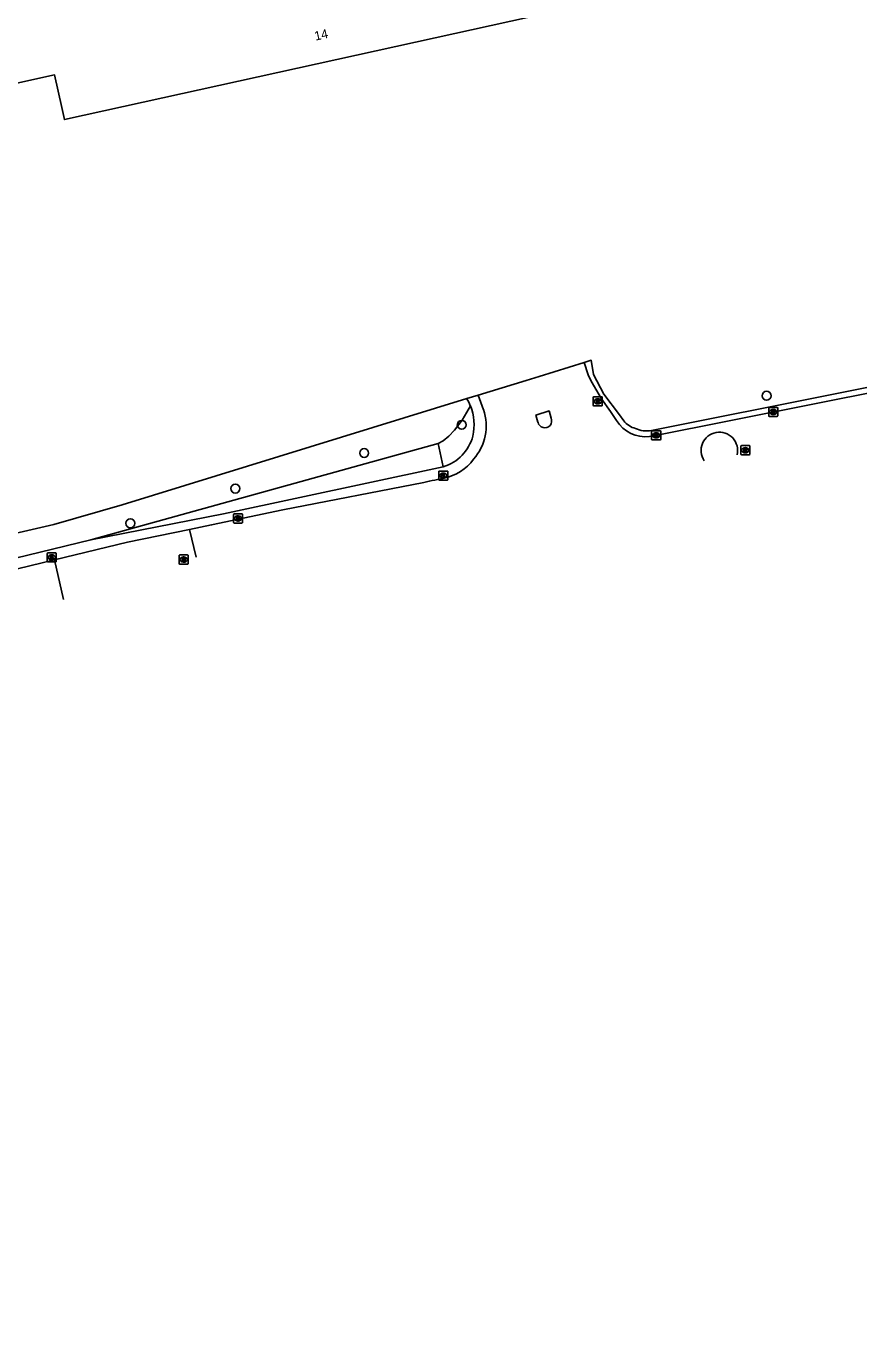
# Model space of a CAD drawing. Extents: x 161477 to 163040, y 383680 to 384868.
# Drawn here: x 162250.6 to 162341.9, y 383711.9 to 383855.4 of the extents above; entities that cross this region are included whole.
import ezdxf

# ---------------------------------------------------------------- set-up
doc = ezdxf.new("R2010")
doc.units = 0
for name, color, linetype in [('IMGEO_Boom', 7, 'Continuous'), ('IMGEO_Groenvoorziening', 7, 'Continuous'), ('IMGEO_Hek', 7, 'Continuous'), ('IMGEO_Kolk', 7, 'Continuous'), ('IMGEO_Pand', 7, 'Continuous'), ('IMGEO_Pand_nummerreeks', 7, 'Continuous'), ('IMGEO_Rijbaan_lokaal_open', 7, 'Continuous'), ('IMGEO_Rioolput', 7, 'Continuous'), ('IMGEO_Voetpad_open', 7, 'Continuous')]:
    doc.layers.add(name, color=color, linetype=linetype)

msp = doc.modelspace()

# ---------------------------------------------------------------- linework, layer by layer
at = {"layer": 'IMGEO_Boom'}
for centre in [(162331.79, 383814.88), (162298.35, 383811.69), (162287.64, 383808.59), (162273.51, 383804.69), (162261.99, 383800.88)]:
    msp.add_circle(centre, 0.489, dxfattribs=at)
at = {"layer": 'IMGEO_Groenvoorziening'}
for points in [[(162298.92, 383814.56), (162261.09, 383802.89), (162253.58, 383800.74), (162226.94, 383794.59), (162215.71, 383792.24), (162200.21, 383788.99), (162072.88, 383760.06), (162061.02, 383757.62), (162034.23, 383752.62), (161913.96, 383727.2), (161882.57, 383720.16), (161862.58, 383715.7), (161851.78, 383713.8), (161847.77, 383713.09), (161846.44, 383712.85), (161845.48, 383712.89), (161845.45, 383711.91)], [(162299.3, 383813.78), (162298.92, 383813.07), (162298.41, 383812.2), (162297.55, 383811.11), (162296.93, 383810.45), (162296.29, 383809.94), (162295.76, 383809.64)], [(162295.76, 383809.64), (162257.67, 383799.06)], [(162296.32, 383807.07), (162295.76, 383809.64)]]:
    msp.add_lwpolyline(points, dxfattribs=at)
at = {"layer": 'IMGEO_Hek'}
msp.add_lwpolyline([(162215.71, 383792.24), (162226.94, 383794.59), (162253.58, 383800.74), (162261.09, 383802.89), (162298.92, 383814.56)], dxfattribs=at)
at = {"layer": 'IMGEO_Kolk'}
for p, q in [((162332.03, 383812.67), (162332.03, 383813.53)), ((162332.1, 383813.6), (162332.96, 383813.6)), ((162332.52, 383813.38), (162332.54, 383813.38)), ((162333.03, 383813.53), (162333.03, 383812.67)), ((162332.96, 383812.6), (162332.1, 383812.6)), ((162332.54, 383812.82), (162332.51, 383812.82)), ((162319.18, 383810.11), (162319.18, 383810.96)), ((162319.26, 383811.03), (162320.11, 383811.03)), ((162319.67, 383810.81), (162319.7, 383810.81)), ((162320.18, 383810.96), (162320.18, 383810.11)), ((162320.11, 383810.03), (162319.26, 383810.03)), ((162319.69, 383810.25), (162319.67, 383810.25)), ((162295.82, 383805.68), (162295.82, 383806.54)), ((162295.9, 383806.61), (162296.75, 383806.61)), ((162296.31, 383806.39), (162296.34, 383806.39)), ((162296.82, 383806.54), (162296.82, 383805.68)), ((162296.75, 383805.61), (162295.9, 383805.61)), ((162296.33, 383805.83), (162296.31, 383805.83)), ((162273.3, 383800.99), (162273.3, 383801.84)), ((162273.38, 383801.91), (162274.23, 383801.91)), ((162274.3, 383801.84), (162274.3, 383800.99)), ((162274.23, 383800.91), (162273.38, 383800.91)), ((162273.79, 383801.69), (162273.81, 383801.69)), ((162273.81, 383801.13), (162273.79, 383801.13)), ((162252.86, 383796.71), (162252.86, 383797.56)), ((162252.93, 383797.64), (162253.79, 383797.64)), ((162253.86, 383797.56), (162253.86, 383796.71)), ((162253.79, 383796.64), (162252.93, 383796.64)), ((162253.35, 383797.42), (162253.37, 383797.42)), ((162253.37, 383796.86), (162253.35, 383796.86))]:
    msp.add_line(p, q, dxfattribs=at)
for points in [[(162332.03, 383812.67), (162332.03, 383813.53)], [(162332.1, 383813.6), (162332.96, 383813.6)], [(162332.35, 383813.3), (162332.47, 383813.3), (162332.47, 383813.15), (162332.6, 383813.3), (162332.77, 383813.3), (162332.62, 383813.15), (162332.77, 383812.9), (162332.62, 383812.9), (162332.54, 383813.06), (162332.47, 383813), (162332.47, 383812.9), (162332.35, 383812.9), (162332.35, 383813.3)], [(162333.03, 383813.53), (162333.03, 383812.67)], [(162332.96, 383812.6), (162332.1, 383812.6)], [(162319.18, 383810.11), (162319.18, 383810.96)], [(162319.26, 383811.03), (162320.11, 383811.03)], [(162319.5, 383810.73), (162319.63, 383810.73), (162319.63, 383810.58), (162319.76, 383810.73), (162319.92, 383810.73), (162319.77, 383810.58), (162319.93, 383810.33), (162319.77, 383810.33), (162319.69, 383810.5), (162319.63, 383810.43), (162319.63, 383810.33), (162319.5, 383810.33), (162319.5, 383810.73)], [(162320.18, 383810.96), (162320.18, 383810.11)], [(162320.11, 383810.03), (162319.26, 383810.03)], [(162295.82, 383805.68), (162295.82, 383806.54)], [(162295.9, 383806.61), (162296.75, 383806.61)], [(162296.14, 383806.31), (162296.27, 383806.31), (162296.27, 383806.16), (162296.4, 383806.31), (162296.56, 383806.31), (162296.42, 383806.16), (162296.57, 383805.91), (162296.42, 383805.91), (162296.33, 383806.07), (162296.27, 383806.01), (162296.27, 383805.91), (162296.14, 383805.91), (162296.14, 383806.31)], [(162296.82, 383806.54), (162296.82, 383805.68)], [(162296.75, 383805.61), (162295.9, 383805.61)], [(162273.3, 383800.99), (162273.3, 383801.84)], [(162273.38, 383801.91), (162274.23, 383801.91)], [(162274.3, 383801.84), (162274.3, 383800.99)], [(162274.23, 383800.91), (162273.38, 383800.91)], [(162273.62, 383801.61), (162273.75, 383801.61), (162273.75, 383801.46), (162273.87, 383801.61), (162274.04, 383801.61), (162273.89, 383801.46), (162274.05, 383801.21), (162273.89, 383801.21), (162273.81, 383801.38), (162273.75, 383801.31), (162273.75, 383801.21), (162273.62, 383801.21), (162273.62, 383801.61)], [(162252.86, 383796.71), (162252.86, 383797.56)], [(162252.93, 383797.64), (162253.79, 383797.64)], [(162253.86, 383797.56), (162253.86, 383796.71)], [(162253.79, 383796.64), (162252.93, 383796.64)], [(162253.18, 383797.34), (162253.3, 383797.34), (162253.3, 383797.19), (162253.43, 383797.34), (162253.6, 383797.34), (162253.45, 383797.19), (162253.6, 383796.94), (162253.45, 383796.94), (162253.37, 383797.1), (162253.3, 383797.03), (162253.3, 383796.94), (162253.18, 383796.94), (162253.18, 383797.34)]]:
    msp.add_lwpolyline(points, dxfattribs=at)
for centre, start, end in [((162332.11, 383813.52), 91.552, 178.448), ((162332.11, 383813.52), 91.552, 178.448), ((162332.95, 383813.52), 1.552, 88.448), ((162332.95, 383813.52), 1.552, 88.448), ((162332.11, 383812.68), 181.552, 268.448), ((162332.11, 383812.68), 181.552, 268.448), ((162332.95, 383812.68), 271.552, 358.448), ((162332.95, 383812.68), 271.552, 358.448), ((162319.26, 383810.96), 91.552, 178.448), ((162319.26, 383810.96), 91.552, 178.448), ((162320.11, 383810.96), 1.552, 88.448), ((162320.11, 383810.96), 1.552, 88.448), ((162319.26, 383810.11), 181.552, 268.448), ((162319.26, 383810.11), 181.552, 268.448), ((162320.11, 383810.11), 271.552, 358.448), ((162320.11, 383810.11), 271.552, 358.448), ((162295.9, 383806.53), 91.552, 178.448), ((162295.9, 383806.53), 91.552, 178.448), ((162296.75, 383806.53), 1.552, 88.448), ((162296.75, 383806.53), 1.552, 88.448), ((162295.9, 383805.69), 181.552, 268.448), ((162295.9, 383805.69), 181.552, 268.448), ((162296.75, 383805.69), 271.552, 358.448), ((162296.75, 383805.69), 271.552, 358.448), ((162273.38, 383801.84), 91.552, 178.448), ((162273.38, 383801.84), 91.552, 178.448), ((162274.23, 383801.84), 1.552, 88.448), ((162274.23, 383801.84), 1.552, 88.448), ((162273.38, 383800.99), 181.552, 268.448), ((162273.38, 383800.99), 181.552, 268.448), ((162274.23, 383800.99), 271.552, 358.448), ((162274.23, 383800.99), 271.552, 358.448), ((162252.94, 383797.56), 91.552, 178.448), ((162252.94, 383797.56), 91.552, 178.448), ((162253.78, 383797.56), 1.552, 88.448), ((162253.78, 383797.56), 1.552, 88.448), ((162252.94, 383796.71), 181.552, 268.448), ((162252.94, 383796.71), 181.552, 268.448), ((162253.78, 383796.71), 271.552, 358.448), ((162253.78, 383796.71), 271.552, 358.448)]:
    msp.add_arc(centre, 0.0765, start, end, dxfattribs=at)
for centre, major_axis, ratio, start_param, end_param in [((162332.52, 383813.1), (-0.387, 0.002), 0.722429, 4.712389, 7.853982), ((162332.54, 383813.1), (-0.39, 0.002), 0.717154, 1.570796, 4.712389), ((162319.67, 383810.53), (-0.387, 0.002), 0.722429, 4.712389, 7.853982), ((162319.69, 383810.53), (-0.39, 0.002), 0.717154, 1.570796, 4.712389), ((162296.31, 383806.11), (-0.387, 0.002), 0.722429, 4.712389, 7.853982), ((162296.33, 383806.11), (-0.39, 0.002), 0.717154, 1.570796, 4.712389), ((162273.79, 383801.41), (-0.387, 0.002), 0.722429, 4.712389, 7.853982), ((162273.81, 383801.41), (-0.39, 0.002), 0.717154, 1.570796, 4.712389), ((162253.35, 383797.14), (-0.387, 0.002), 0.722429, 4.712389, 7.853982), ((162253.37, 383797.14), (-0.39, 0.002), 0.717154, 1.570796, 4.712389)]:
    msp.add_ellipse(centre, major_axis=major_axis, ratio=ratio, start_param=start_param, end_param=end_param, dxfattribs=at)
at = {"layer": 'IMGEO_Pand'}
msp.add_lwpolyline([(162222.78, 383843.26), (162253.68, 383850.09), (162254.46, 383846.53), (162254.76, 383845.19), (162312.37, 383857.91), (162312.05, 383859.38), (162421.56, 383883.57), (162417.41, 383902.34), (162405.62, 383899.74)], dxfattribs=at)
at = {"layer": 'IMGEO_Rijbaan_lokaal_open'}
for points in [[(162395.79, 383826.38), (162380.16, 383823.26), (162319.15, 383811.08)], [(162379.65, 383822.47), (162319.24, 383810.45), (162318.95, 383810.39)], [(162311.78, 383818.53), (162306.83, 383817), (162305.42, 383816.57), (162300.16, 383814.95)], [(162316.14, 383812.14), (162315.67, 383812.77), (162313.95, 383815.04), (162312.8, 383817.2), (162312.56, 383818.77), (162311.78, 383818.53)], [(162315.33, 383812.15), (162314.66, 383813.15), (162313.68, 383814.54), (162312.55, 383816.49), (162312.22, 383817.18), (162311.78, 383818.53)], [(162300.16, 383814.95), (162300.74, 383813.35)], [(162306.71, 383811.97), (162306.49, 383812.75), (162307.92, 383813.21), (162308.15, 383812.42)], [(162296.37, 383805.82), (162296.01, 383805.74), (162295.7, 383805.68), (162295.4, 383805.62), (162295.09, 383805.56), (162294.79, 383805.49), (162294.48, 383805.43), (162294.18, 383805.37), (162278.73, 383802.34), (162270.9, 383800.71), (162268.48, 383800.21)], [(162268.48, 383800.21), (162261.67, 383798.79), (162253.66, 383796.86)], [(162269.21, 383797.16), (162268.48, 383800.21)], [(162253.66, 383796.86), (162244.29, 383794.61), (162240.84, 383793.55), (162224.8, 383788.56), (162219.62, 383786.85), (162219.33, 383786.78), (162214.48, 383785.25), (162201.98, 383781.65), (162200.19, 383781.17), (162199.34, 383780.94), (162193.85, 383779.62), (162173.23, 383775.14), (162160.65, 383772.41), (162129.52, 383765.69), (162103.41, 383760.08), (162086.49, 383756.59), (162061.51, 383751.2), (162055.16, 383749.81), (162038.61, 383746.29), (162000, 383738.01)], [(162253.66, 383796.86), (162254.66, 383792.5)]]:
    msp.add_lwpolyline(points, dxfattribs=at)
for centre, radius, start, end in [((162295.45, 383811.59), 5.58, 318.7426, 18.4435), ((162307.46, 383812.11), 0.759, 190.181, 24.5952), ((162318.53, 383814.12), 3.75, 211.5389, 276.3751), ((162317.96, 383813.5), 2.28, 216.7152, 256.2761), ((162318.57, 383813.49), 2.48, 242.3013, 283.5464), ((162326.61, 383808.88), 2, 100.0945, 214.3745), ((162326.61, 383808.88), 2, 345.8313, 100.0996), ((162295.24, 383811.21), 5.51, 281.859, 323.1128)]:
    msp.add_arc(centre, radius, start, end, dxfattribs=at)
at = {"layer": 'IMGEO_Rioolput'}
for p, q in [((162312.77, 383813.84), (162312.77, 383814.69)), ((162312.84, 383814.76), (162313.69, 383814.76)), ((162313.77, 383814.69), (162313.77, 383813.84)), ((162313.69, 383813.76), (162312.84, 383813.76)), ((162313.25, 383814.54), (162313.28, 383814.54)), ((162313.28, 383813.98), (162313.25, 383813.98)), ((162328.96, 383808.48), (162328.96, 383809.33)), ((162329.04, 383809.41), (162329.89, 383809.41)), ((162329.45, 383809.18), (162329.47, 383809.18)), ((162329.96, 383809.33), (162329.96, 383808.48)), ((162329.89, 383808.4), (162329.04, 383808.4)), ((162329.47, 383808.63), (162329.45, 383808.63)), ((162267.33, 383796.47), (162267.33, 383797.32)), ((162267.41, 383797.4), (162268.26, 383797.4)), ((162268.26, 383796.4), (162267.41, 383796.4)), ((162267.82, 383797.18), (162267.85, 383797.18)), ((162267.84, 383796.62), (162267.82, 383796.62)), ((162268.34, 383797.32), (162268.34, 383796.47))]:
    msp.add_line(p, q, dxfattribs=at)
for points in [[(162312.77, 383813.84), (162312.77, 383814.69)], [(162312.84, 383814.76), (162313.69, 383814.76)], [(162313.77, 383814.69), (162313.77, 383813.84)], [(162313.69, 383813.76), (162312.84, 383813.76)], [(162313.35, 383814.46), (162313.1, 383814.46), (162313.1, 383814.06)], [(162313.1, 383814.06), (162313.23, 383814.06), (162313.23, 383814.23), (162313.24, 383814.23)], [(162313.28, 383814.38), (162313.23, 383814.38), (162313.23, 383814.3)], [(162313.23, 383814.3), (162313.28, 383814.3)], [(162313.28, 383814.2), (162313.36, 383814.06), (162313.49, 383814.06), (162313.43, 383814.19)], [(162328.96, 383808.48), (162328.96, 383809.33)], [(162329.04, 383809.41), (162329.89, 383809.41)], [(162329.55, 383809.1), (162329.3, 383809.1), (162329.3, 383808.7)], [(162329.48, 383809.02), (162329.42, 383809.02), (162329.42, 383808.94)], [(162329.42, 383808.94), (162329.47, 383808.94)], [(162329.96, 383809.33), (162329.96, 383808.48)], [(162329.89, 383808.4), (162329.04, 383808.4)], [(162329.3, 383808.7), (162329.42, 383808.7), (162329.42, 383808.87), (162329.43, 383808.87)], [(162329.48, 383808.84), (162329.55, 383808.7), (162329.69, 383808.7), (162329.63, 383808.83)], [(162267.33, 383796.47), (162267.33, 383797.32)], [(162267.41, 383797.4), (162268.26, 383797.4)], [(162268.26, 383796.4), (162267.41, 383796.4)], [(162267.92, 383797.1), (162267.67, 383797.1), (162267.67, 383796.7)], [(162267.67, 383796.7), (162267.8, 383796.7), (162267.8, 383796.86), (162267.81, 383796.86)], [(162267.85, 383797.02), (162267.8, 383797.02), (162267.8, 383796.94)], [(162267.8, 383796.94), (162267.85, 383796.94)], [(162267.85, 383796.83), (162267.92, 383796.7), (162268.06, 383796.7), (162268, 383796.82)], [(162268.34, 383797.32), (162268.34, 383796.47)]]:
    msp.add_lwpolyline(points, dxfattribs=at)
for centre, radius, start, end in [((162312.84, 383814.69), 0.0765, 91.552, 178.448), ((162312.84, 383814.69), 0.0765, 91.552, 178.448), ((162313.69, 383814.69), 0.0765, 1.552, 88.448), ((162313.69, 383814.69), 0.0765, 1.552, 88.448), ((162312.84, 383813.84), 0.0765, 181.552, 268.448), ((162312.84, 383813.84), 0.0765, 181.552, 268.448), ((162313.24, 383814.17), 0.0533, 26.0293, 88.6989), ((162313.29, 383814.29), 0.0964, 77.0061, 93.1865), ((162313.26, 383814.49), 0.19, 274.7715, 282.9687), ((162313.3, 383814.34), 0.0378, 276.6634, 79.6772), ((162313.35, 383814.35), 0.109, 350.3612, 89.416), ((162313.35, 383814.35), 0.112, 277.5842, 350.9817), ((162313.34, 383814.14), 0.108, 29.5134, 73.7905), ((162313.69, 383813.84), 0.0765, 271.552, 358.448), ((162313.69, 383813.84), 0.0765, 271.552, 358.448), ((162329.04, 383809.33), 0.0765, 91.552, 178.448), ((162329.04, 383809.33), 0.0765, 91.552, 178.448), ((162329.46, 383809.13), 0.19, 274.7715, 282.9687), ((162329.48, 383808.93), 0.0964, 77.0061, 93.1865), ((162329.5, 383808.98), 0.0378, 276.6634, 79.6772), ((162329.55, 383808.99), 0.109, 350.3612, 89.416), ((162329.55, 383808.99), 0.112, 277.5842, 350.9817), ((162329.89, 383809.33), 0.0765, 1.552, 88.448), ((162329.89, 383809.33), 0.0765, 1.552, 88.448), ((162329.04, 383808.48), 0.0765, 181.552, 268.448), ((162329.04, 383808.48), 0.0765, 181.552, 268.448), ((162329.43, 383808.81), 0.0533, 26.0293, 88.6989), ((162329.53, 383808.78), 0.108, 29.5134, 73.7905), ((162329.89, 383808.48), 0.0765, 271.552, 358.448), ((162329.89, 383808.48), 0.0765, 271.552, 358.448), ((162267.41, 383797.32), 0.0765, 91.552, 178.448), ((162267.41, 383797.32), 0.0765, 91.552, 178.448), ((162267.41, 383796.47), 0.0765, 181.552, 268.448), ((162267.41, 383796.47), 0.0765, 181.552, 268.448), ((162267.8, 383796.81), 0.0533, 26.0293, 88.6989), ((162267.85, 383796.92), 0.0964, 77.0061, 93.1865), ((162267.83, 383797.13), 0.19, 274.7715, 282.9687), ((162267.87, 383796.98), 0.0378, 276.6634, 79.6772), ((162267.92, 383796.99), 0.109, 350.3612, 89.416), ((162267.92, 383796.99), 0.112, 277.5842, 350.9817), ((162267.9, 383796.77), 0.108, 29.5134, 73.7905), ((162268.26, 383797.32), 0.0765, 1.552, 88.448), ((162268.26, 383797.32), 0.0765, 1.552, 88.448), ((162268.26, 383796.47), 0.0765, 271.552, 358.448), ((162268.26, 383796.47), 0.0765, 271.552, 358.448)]:
    msp.add_arc(centre, radius, start, end, dxfattribs=at)
for centre, major_axis, ratio, start_param, end_param in [((162313.25, 383814.26), (-0.387, 0.002), 0.722429, 4.712389, 7.853982), ((162313.28, 383814.26), (-0.39, 0.002), 0.717154, 1.570796, 4.712389), ((162329.45, 383808.9), (-0.387, 0.002), 0.722429, 4.712389, 7.853982), ((162329.47, 383808.9), (-0.39, 0.002), 0.717154, 1.570796, 4.712389), ((162267.82, 383796.9), (-0.387, 0.002), 0.722429, 4.712389, 7.853982), ((162267.85, 383796.9), (-0.39, 0.002), 0.717154, 1.570796, 4.712389)]:
    msp.add_ellipse(centre, major_axis=major_axis, ratio=ratio, start_param=start_param, end_param=end_param, dxfattribs=at)
at = {"layer": 'IMGEO_Voetpad_open'}
for points in [[(162300.16, 383814.95), (162298.92, 383814.56)], [(162257.67, 383799.06), (162272.19, 383801.91), (162296.32, 383807.07)], [(162231.35, 383791.72), (162238.76, 383794.1), (162245.14, 383796.02), (162257.67, 383799.06)]]:
    msp.add_lwpolyline(points, dxfattribs=at)
for centre, radius, start, end in [((162293.81, 383811.61), 5.89, 21.5643, 30.0357), ((162293.93, 383811.67), 5.77, 347.7831, 21.4277), ((162294.88, 383811.7), 4.85, 287.2964, 345.1082)]:
    msp.add_arc(centre, radius, start, end, dxfattribs=at)

# ---------------------------------------------------------------- texts
at = {"layer": 'IMGEO_Pand_nummerreeks'}
msp.add_text('14', height=1, rotation=12.5019, dxfattribs=at).set_placement((162282.3, 383853.85))

doc.saveas('drawing.dxf')
